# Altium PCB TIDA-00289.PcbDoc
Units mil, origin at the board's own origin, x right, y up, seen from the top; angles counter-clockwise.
Board outline 1181.1 x 984.25 mil, 4 copper layers (Top Layer, MidLayer1 (GND), MidLayer2 (PWR), Bottom Layer), stack 90 mil thick; 82 components, 47 nets, 196 pads, 38 vias.
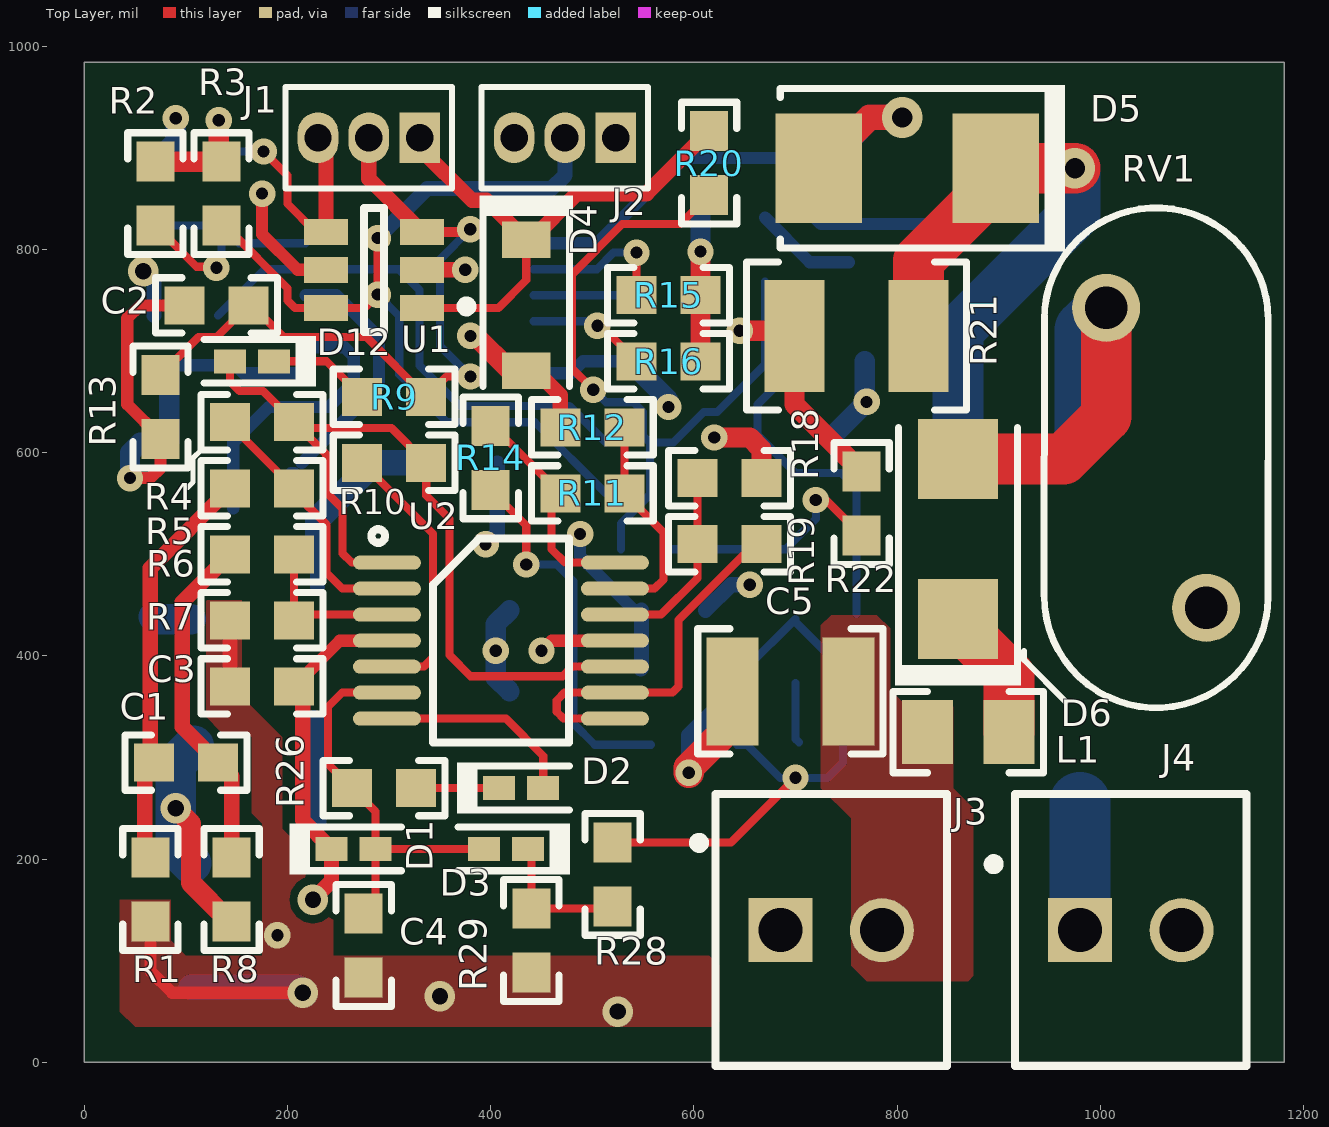
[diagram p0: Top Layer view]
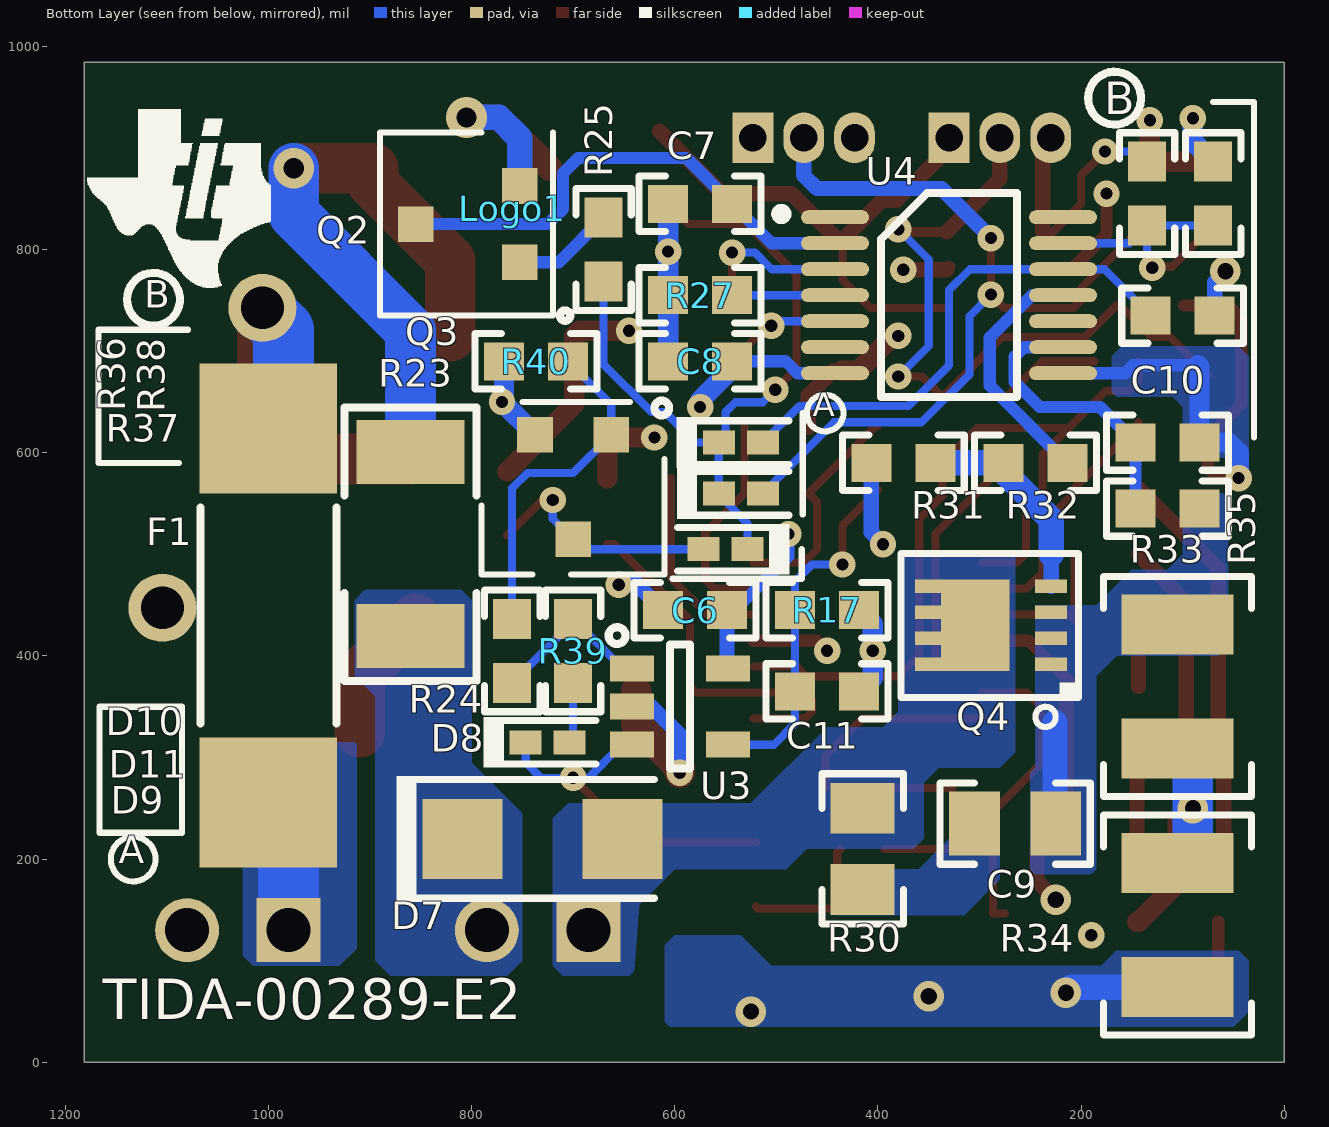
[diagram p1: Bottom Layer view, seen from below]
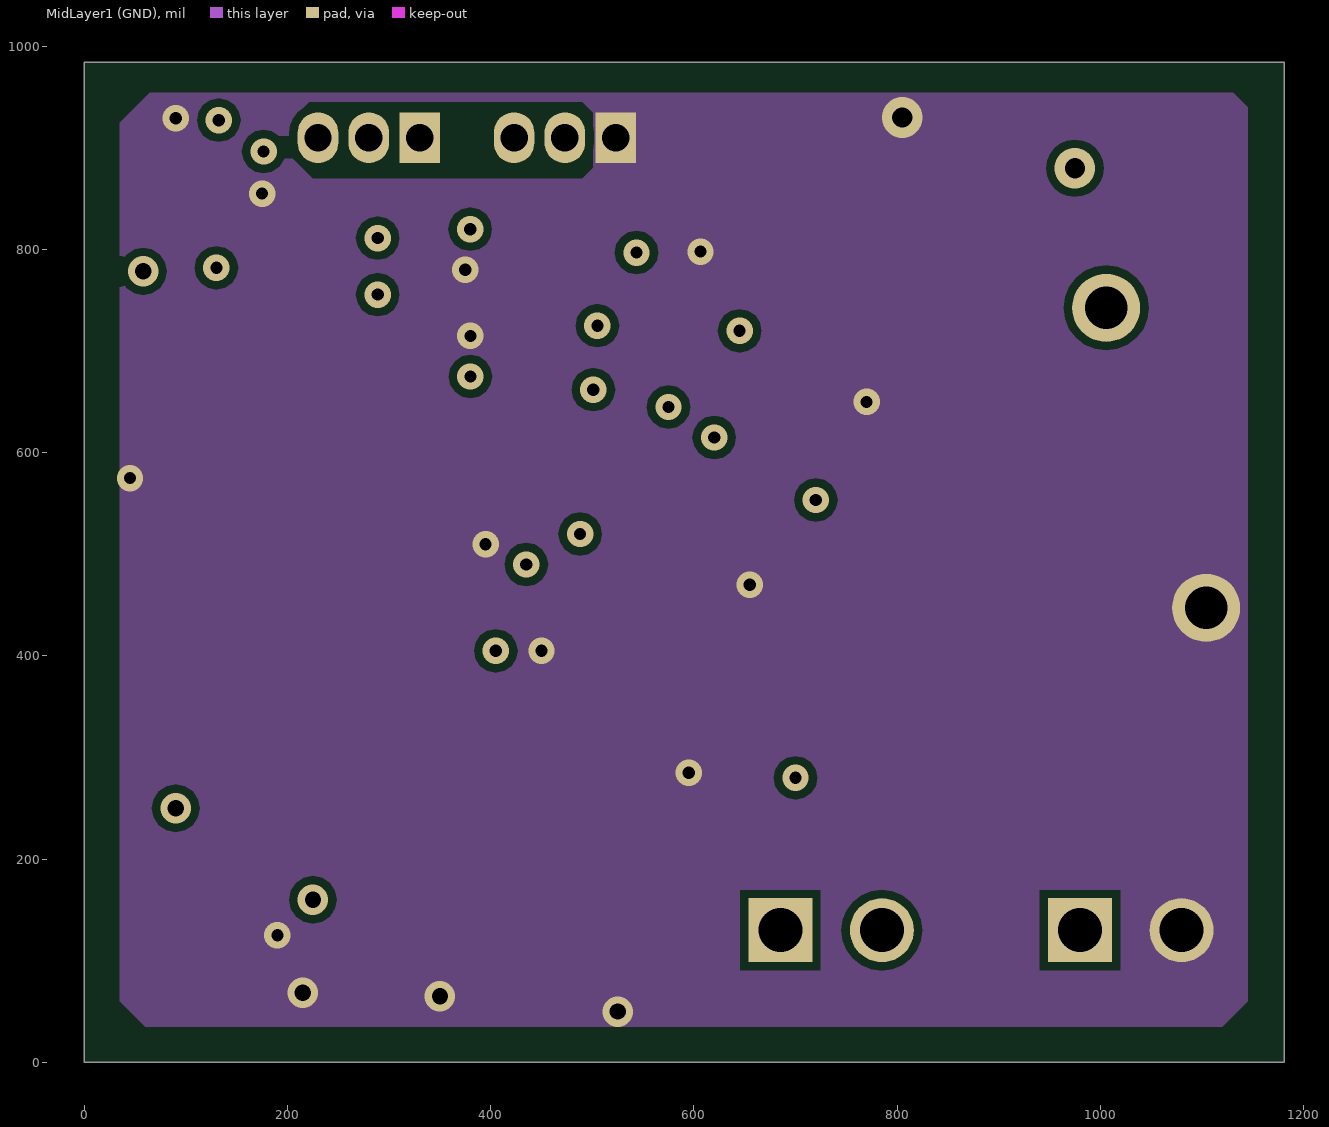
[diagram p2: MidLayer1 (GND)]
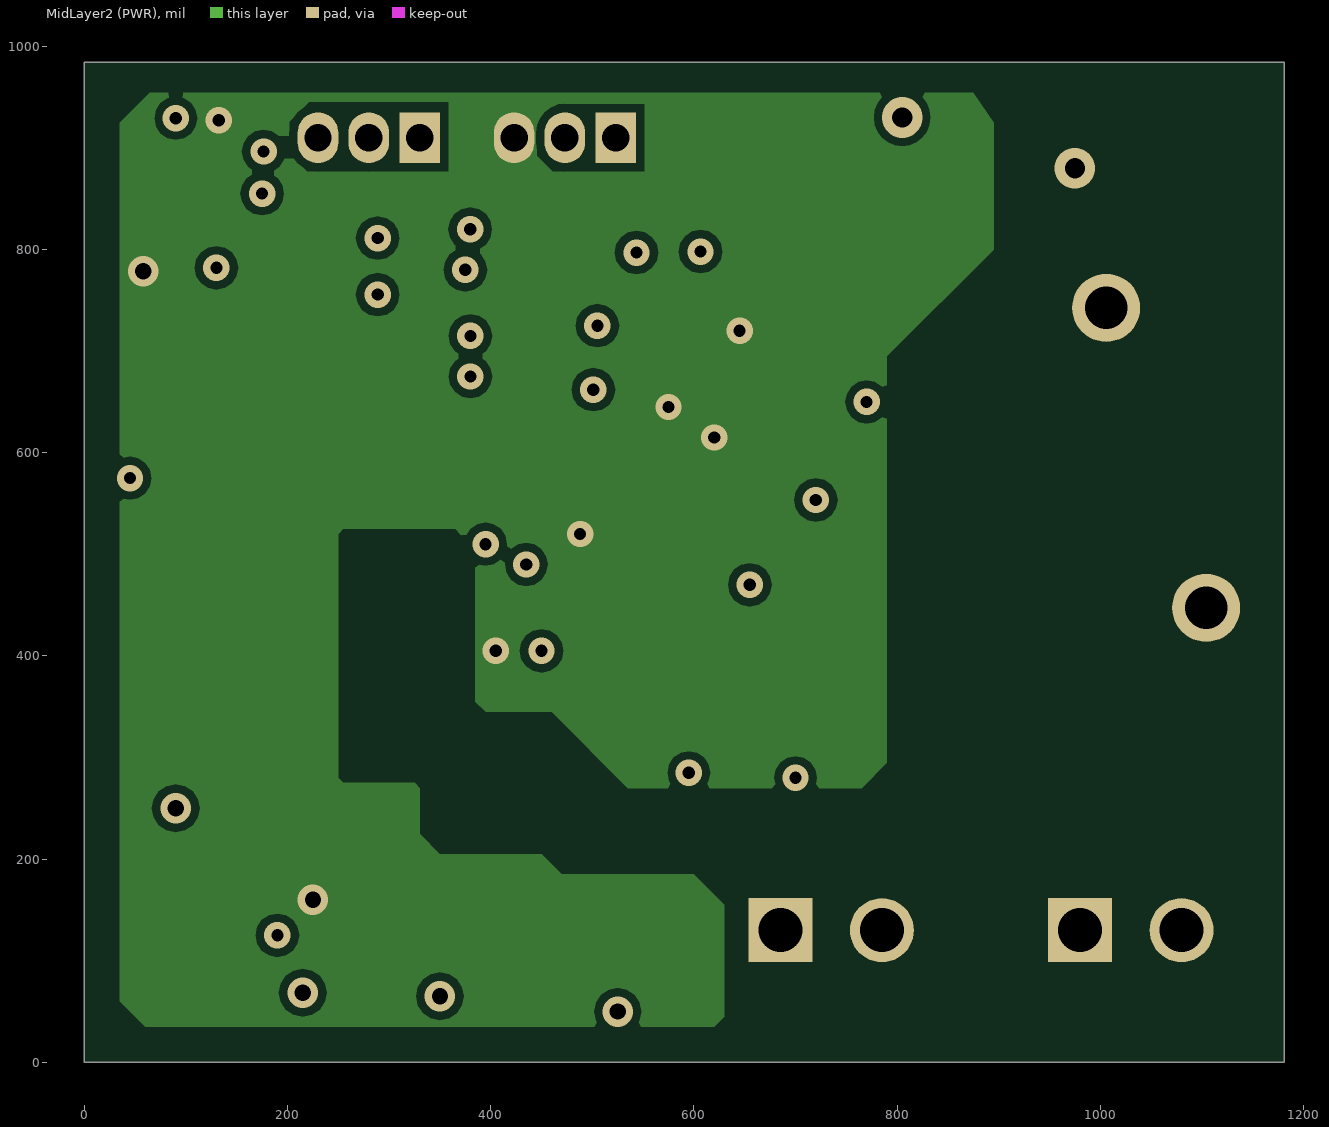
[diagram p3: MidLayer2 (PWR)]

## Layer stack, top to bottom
Top Layer: signal copper 1.4
Dielectric: core 59.2, FR-4, Dk 4.8
MidLayer1 (GND): signal copper 1.4
Dielectric: prepreg 12.6, FR-4, Dk 4.8
MidLayer2 (PWR): signal copper 1.4
Dielectric: core 12.6, FR-4, Dk 4.8
Bottom Layer: signal copper 1.4

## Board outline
0,0 1181.1,0 1181.1,984.25 0,984.25

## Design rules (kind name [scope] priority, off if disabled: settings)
AcuteAngle [All] p1: minimum=4.50000000000000E+0001 checktracksonly=FALSE
AssemblyTestPointUsage [All] p1: valid=2
Clearance "Less Than 9 mils from PAD to PAD" [(InPadClass('Less than 9 Mil Clearance')) vs (InPadClass('All Pads'))] p1: gap=7
Clearance "SMT Pin Via" [IsVia vs IsSMTPin] p2: gap=8
Clearance "Via to Via" [IsVia vs IsVia] p3: gap=8
Clearance Poly_Poly [InPolygon vs InPolygon] p4: gap=15
Clearance "Poly_ All" [InPolygon vs IsTrack and IsThruPin and IsSMTPin and IsThruPin] p5: gap=12
Clearance [All] p6: gap=8
ComponentClearance ComponentClearance_Shunt [InComponentClass('Header') vs InComponentClass('Shunt')] p1: gap=0 collisioncheckmode=3 verticalgap=0 showdistances=FALSE
ComponentClearance ComponentClearance_Logo [InComponentClass('Logo')] p2: gap=50 collisioncheckmode=3 verticalgap=10 showdistances=FALSE
ComponentClearance ComponentClearance_ScrewToNut [(HasFootprint('NY PMS 440 0025 PH')) vs (HasFootprint('Keystone_1902C'))] p3: gap=5 collisioncheckmode=3 verticalgap=10 showdistances=FALSE
ComponentClearance ComponentClearance_MountingHoles [InComponentClass('Mounting Holes')] p4: gap=250 collisioncheckmode=3 verticalgap=100000 showdistances=FALSE
ComponentClearance ComponentClearance_SmallPassives [HasFootprint('0201*') or HasFootprint('0402*') or HasFootprint('0508') or HasFootprint('0603*') or HasFootprint('0612') or HasFootprint('0805*') or HasFootprint('0815*') or HasFootprint('0830*') or HasFootprint('1206*') or HasFootprint('1210*') or HasFootprint('1808*') or HasFootprint('1812*') or HasFootprint('1825*') or HasFootprint('2010*') or HasFootprint('2220*') or HasFootprint('2225*') or HasFootprint('2512*') or HasFootprint('2728*') or HasFootprint('3518*') vs HasFootprint('0201*') or HasFootprint('0402*') or HasFootprint('0508') or HasFootprint('0603*') or HasFootprint('0612') or HasFootprint('0805*') or HasFootprint('0815*') or HasFootprint('0830*') or HasFootprint('1206*') or HasFootprint('1210*') or HasFootprint('1808*') or HasFootprint('1812*') or HasFootprint('1825*') or HasFootprint('2010*') or HasFootprint('2220*') or HasFootprint('2225*') or HasFootprint('2512*') or HasFootprint('2728*') or HasFootprint('3518*')] p5: gap=20 collisioncheckmode=3 verticalgap=10 showdistances=FALSE
ComponentClearance ComponentClearance_THtoSMT [IsThruComponent vs IsSMTComponent] p6: gap=100 collisioncheckmode=3 verticalgap=30 showdistances=FALSE
ComponentClearance ComponentClearance_THtoTH [IsThruComponent vs IsThruComponent] p7: gap=118.11 collisioncheckmode=3 verticalgap=30 showdistances=FALSE
ComponentClearance [All] p8: gap=40 collisioncheckmode=3 verticalgap=10 showdistances=FALSE
DiffPairsRouting [All] p1: maxlimit=100 minlimit=10 mostfreqgap=10 maxuncoupledlength=1000
FabricationTestPointUsage TestPointUsage [All] p1: valid=2 allowmultiple=FALSE
FabricationTestpoint Testpoint [All] p1: side=3 testpointundercomponent=TRUE minsize=40 maxsize=100 preferedsize=60 minholesize=0 maxholesize=40 preferedholesize=32 testpointgrid=1 allowsidetop=TRUE allowsidebottom=TRUE usegrid=TRUE gridtolerance=0.01
FanoutControl Fanout_LCC [IsLCC] p1: bgadir=Out bgaviamode=Centered fanoutstyle=Auto fanoutdirection=Alternating viagrid=1 // Fanout_LCC (Default Rule)
FanoutControl Fanout_BGA [IsBGA] p2: bgadir=Out bgaviamode=Centered fanoutstyle=Auto fanoutdirection=Alternating viagrid=1 // Fanout_BGA (Default Rule)
FanoutControl Fanout_Default [All] p4: bgadir=Out bgaviamode=Centered fanoutstyle=Auto fanoutdirection=Alternating viagrid=1 // Fanout_Default (Default Rule)
FanoutControl Fanout_Small [(CompPinCount < 5)] p5: bgadir=Out bgaviamode=Centered fanoutstyle=Auto fanoutdirection=OutThenIn viagrid=1 // Fanout_Small (Default Rule)
HoleSize [All] p1: absolutevalues=TRUE maxlimit=251 minlimit=8 maxpercent=80.000 minpercent=20.000
MinimumAnnularRing MinimumAnnularRing_ThermalPadVias [IsVia and InAnyComponent] p1: minimumring=5.91
MinimumAnnularRing [All] p2: minimumring=5.91
MinimumSolderMaskSliver MinimumSolderMaskSliver_Logo [InComponentClass('Logo') vs InComponentClass('Logo')] p1: minsoldermaskwidth=0.7
MinimumSolderMaskSliver [All] p2: minsoldermaskwidth=3.94
PlaneConnect [All] p1: planeconnectstyle=Relief reliefexpansion=10 reliefentries=4 reliefconductorwidth=10 reliefairgap=10
PolygonConnect [All] p1: connectstyle=Direct reliefconductorwidth=10 reliefentries=4 polygonreliefangle="90 Angle" airgapwidth=10
RoutingVias [All] p1: holewidth=12 width=26 viastyle="Through Hole" minholewidth=12 minwidth=26 maxholewidth=20 maxwidth=40
SMDToCorner [All] p1: distance=30000
SilkToSilkClearance [All] p1: silktosilkclearance=5
SilkscreenOverComponentPads [All] p1: minsilkscreentomaskgap=5
SolderMaskExpansion [All] p1: expansion=2.5
Width [All] p1: maxlimit=100 minlimit=8 preferedwidth=8 checkconnectedcopper=TRUE
14 further rules are at their usual default settings.

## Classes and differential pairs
pad class "Less than 9 Mil Clearance": U1-1 U1-2 U1-3 U1-4 U1-5 U1-6 U1-7 U1-8 U1-9 U1-10 U1-11 U1-12 U1-13 U1-14 U2-1 U2-2 U2-3 U2-4 U2-5 U2-6 U2-7 U2-8
component class Pg2-Main: C1 C2 C3 C4 C5 C6 C7 C8 C9 C10 C11 D1 D2 D3 D4 D5 D6 D7 D8 D9 D10 D11 D12 F1 J1 J2 J3 J4 L1 Q2 Q3 Q4 R1 R2 R3 R4 R5 R6 R7 R8 R9 R10 R11 R12 R13 R14 R15 R16 R17 R18 R19 R20 R21 R22 R23 R24 R25 R26 R27 R28 R29 R30 R31 R32 R33 R34 R35 R36 R37 R38 R39 R40 RV1 U1 U2 U3 U4
component class AssemblyNote: ZZ1 ZZ2 ZZ3 ZZ4
component class Pg3_Hardware_ANSI-B: !PCB Logo1 ZZ1 ZZ2 ZZ3 ZZ4
component class Logo: Logo1

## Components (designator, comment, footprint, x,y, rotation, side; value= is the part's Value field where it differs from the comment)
C1 "06035A101JAT2A" 0603 100,295 r180 top (schematic designator C9)
C2 "GRM188R71E104KA01D" 0603 130,745 r180 top (schematic designator C7)
C3 "GRM188R71E104KA01D" 0603 175,370 r0 top (schematic designator C5)
C4 "GRM188R71E474KA12D" 0603 275,115 r270 top (schematic designator C6)
C5 "C3225X7R2A105K200AA" 1210 695,365 r180 top (schematic designator C4)
C6 "GRM188R71E104KA01D" 0603 580,445 r180 bottom (schematic designator C10)
C7 "C0603C105K8PACTU" 0603 575,845 r180 bottom (schematic designator C2)
C8 "GMK107BJ105KA-T" 0603 575,690 r0 bottom (schematic designator C1)
C9 "08051C103KAT2A" 0805_HV 265,235 r180 bottom (schematic designator C7)
C10 "06035A101JAT2A" 0603 115,610 r180 bottom (schematic designator C3)
C11 "GRM188R71E472KA01D" 0603 450,365 r180 bottom
D1 "NSR0520V2T1G" SOD-523#1 265,210 r0 top (schematic designator D11)
D2 "NSR0520V2T1G" SOD-523#2 430,270 r0 top (schematic designator D6)
D3 "NSR0520V2T1G" SOD-523#2 415,210 r180 top (schematic designator D5)
D4 "MMSZ5240B-7-F" SOD-123 435,745 r270 top (schematic designator D10)
D5 "SMBJ5357B-TP" SMB 810,880 r180 top (schematic designator D3)
D6 "CMR1U-02M" SMA 860,515 r90 top (schematic designator D5)
D7 "US1B-13-F" SMA 730,220 r180 bottom (schematic designator D2)
D8 "NSR0520V2T1G" SOD-523#2 725,315 r180 bottom (schematic designator D7)
D9 "NSR0520V2T1G" SOD-523#2 550,505 r0 bottom
D10 "NSR0520V2T1G" SOD-523#2 535,610 r180 bottom (schematic designator D1)
D11 "NSR0520V2T1G" SOD-523#2 535,560 r180 bottom (schematic designator D8)
D12 "NSR0520V2T1G" SOD-523#1 165,690 r180 top
F1 "0443.500DR" FUSE_0443 1000,440 r270 bottom
J1 "800-10-003-10-001000" CONNECTOR_GRPB031VWVN-RC 330,910 r180 top (schematic designator J5)
J2 "800-10-003-10-001000" CONNECTOR_GRPB031VWVN-RC 523,910 r180 top (schematic designator J4)
J3 "282834-2" TEC_282834-2 735,130 r0 top (schematic designator J2)
J4 "282834-2" TEC_282834-2 1030,130 r0 top (schematic designator J1)
L1 "LQM21PN2R2NGC" 0805_HV 870,325 r180 top
Logo1 "Texas Instruments" TI_Stacked_SolderMask_Small 760,840 r180 bottom
Q2 "TR-BC850" SOT-23 805,825 r90 bottom
Q3 "TR-BC850" SOT-23 700,565 r0 bottom
Q4 "BSZ440N10NS3 G" PG-TSDSON-8 290,430 r0 bottom (schematic designator Q1)
R1 "RC0603FR-071KL" 0603 65,170 r270 top (schematic designator R33)
R2 "RT0603BRD0710KL" 0603 70,855 r90 top (schematic designator R11)
R3 "RT0603BRD0710KL" 0603 135,855 r270 top (schematic designator R13)
R4 "CRCW0603100KFKEA" 0603 175,630 r180 top (schematic designator R16)
R5 "RC0603FR-071KL" 0603 175,565 r180 top (schematic designator R20)
R6 "RC0603FR-071KL" 0603 175,500 r180 top (schematic designator R24)
R7 "CRCW0603100KFKEA" 0603 175,435 r0 top (schematic designator R25)
R8 "RC0603FR-071KL" 0603 145,170 r90 top (schematic designator R32)
R9 "RC0603FR-071KL" 0603 305,655 r0 top (schematic designator R1)
R10 "RT0603BRD0710KL" 0603 305,590 r0 top (schematic designator R38)
R11 "RC0603FR-071KL" 0603 500,560 r180 top (schematic designator R31)
R12 "CRCW0603100KFKEA" 0603 500,625 r0 top (schematic designator R35)
R13 "CRCW0603100KFKEA" 0603 75,645 r90 top (schematic designator R29)
R14 "RC0603FR-071KL" 0603 400,595 r270 top (schematic designator R30)
R15 "CRCW0603100KFKEA" 0603 575,755 r0 top (schematic designator R4)
R16 "CRCW06030000Z0EA" 0603 575,690 r0 top (schematic designator R2)
R17 "CRCW0603100KFKEA" 0603 450,445 r0 bottom (schematic designator R37)
R18 "CRCW0603100KFKEA" 0603 635,575 r180 top
R19 "RC0603FR-071KL" 0603 635,510 r180 top (schematic designator R23)
R20 "RC0603FR-071KL" 0603 615,885 r90 top (schematic designator R36)
R21 "MCR25JZHJ000" 1210M 760,715 r0 top (schematic designator R7)
R22 "CRCW060320K0FKEA" 0603 765,550 r270 top (schematic designator R15)
R23 "CRCW2010430KJNEF" 2010 860,510 r270 bottom (schematic designator R8)
R24 "RT0603BRD0710KL" 0603 760,405 r270 bottom (schematic designator R22)
R25 "CRCW0603196KFKEA" 0603 670,800 r90 bottom (schematic designator R34)
R26 "CRCW0603100RFKEA" 0603 295,270 r180 top (schematic designator R28)
R27 "CRCW060351R1FKEA" 0603 575,755 r0 bottom (schematic designator R3)
R28 "RT0603BRD0710KL" 0603 520,185 r90 top (schematic designator R26)
R29 "CRCW0603196KFKEA" 0603 440,120 r90 top (schematic designator R27)
R30 "RT0805BRD07100RL" 0805_HV 415,210 r90 bottom (schematic designator R14)
R31 "RC0603FR-071KL" 0603 375,590 r180 bottom (schematic designator R12)
R32 "CRCW06030000Z0EA" 0603 245,590 r180 bottom (schematic designator R10)
R33 "MCR25JZHFLR390" 1210M 105,370 r90 bottom (schematic designator R6)
R34 "MCR25JZHFLR200" 1210M 105,135 r90 bottom (schematic designator R19)
R35 "RC0603FR-071KL" 0603 115,545 r180 bottom (schematic designator R5)
R36 "RT0603BRD0710KL" 0603 135,855 r90 bottom (schematic designator R21)
R37 "CRCW060320K0FKEA" 0603 100,735 r180 bottom (schematic designator R9)
R38 "CRCW06032K00JNEA" 0603 70,855 r270 bottom (schematic designator R17)
R39 "CRCW06030000Z0EA" 0603 700,405 r90 bottom
R40 "RT0603BRD0710KL" 0603 736.5,690 r180 bottom
RV1 "V100ZA4P" VAR_V100ZA4P 1055,595 r90 top
U1 "SMS12T1G" DBV0006A_N 285,780 r180 top (schematic designator U3)
U2 "OPA4170AIPW" PW0014A_N 410,415 r0 top (schematic designator U4)
U3 "TLV271IDBVR" DBV0005A_N 595,350 r180 bottom (schematic designator U2)
U4 "DRV110APW" PW0014A_N 330,755 r180 bottom (schematic designator U1)
ZZ1 "This Assembly Note is for PCB labels only" AssemblyNoteLabel -250,1480 r0 top
ZZ2 "These assemblies are ESD sensitive, ESD precautions shall be observed." AssemblyNote -250,1410 r0 top
ZZ3 "These assemblies must be clean and free from flux and all contaminants. Use of no clean flux is not acceptable." AssemblyNote -250,1340 r0 top
ZZ4 "These assemblies must comply with workmanship standards IPC-A-610 Class 2, unless otherwise specified." AssemblyNote -250,1270 r0 top

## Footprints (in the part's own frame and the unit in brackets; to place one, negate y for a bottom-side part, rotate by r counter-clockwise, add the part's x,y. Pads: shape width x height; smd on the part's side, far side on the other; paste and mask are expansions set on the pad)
0603 [mm] "0603 from SM-752 data"
  rect 1x0.95 smd: 1(-0.8,0) 2(0.8,0)
  silkscreen extent -1.52,-0.69 1.52,0.69, body extent -0.87,-0.47 0.87,0.47, height 0.85
0805_HV [mil] "0805 with 30mil clearance between pads"
  rect 50x63 smd: 1(-40,0) 2(40,0)
  silkscreen extent -74,-40 74,40, body extent -43,-29 43,29, height 43
1210 [mm] "1210 from SM-752 data"
  rect 1.3x2.7 smd: 1(-1.45,0) 2(1.45,0)
  silkscreen extent -2.32,-1.57 2.32,1.57, body extent -1.7,-1.35 1.7,1.35, height 1.35
1210M [mm] "1210 from SM-752 data"
  rect 1.5x2.8 smd: 1(-1.55,0) 2(1.55,0)
  silkscreen extent -2.75,-1.85 2.75,1.85, body extent -1.7,-1.35 1.7,1.35, height 1.35
2010 [mm] "Chip Capacitor, Body 5.08x2.54mm, IPC Medium Density"
  rect 1.6x2.7 smd: 1(-2.3,0) 2(2.3,0)
  silkscreen extent -3.42,-1.65 3.42,1.65, body extent -2.73,-1.45 2.73,1.45, height 1.66
AssemblyNote [mil] "Assembly Note"
AssemblyNoteLabel [mil] "Assembly Note for PCB Labels"
CONNECTOR_GRPB031VWVN-RC [mil] "CONN HEADER .050\" 3POS PCB GOLD"
  rect 40x50 hole 27: 1(0,0)
  oval 40x50 hole 27: 2(50,0) 3(100,0)
  silkscreen extent -32,-50 132,50, body extent -32,-50 132,50, height 150
DBV0005A_N [mm] "SOT23, 5-Leads, Body 2.9x1.6mm, Pitch 0.95mm, Lead Span 2.8mm, IPC Medium Density"
  rect 1.1x0.65 smd: 1(-1.2,0.95) 2(-1.2,0) 3(-1.2,-0.95) 4(1.2,-0.95) 5(1.2,0.95)
  silkscreen extent -0.25,-1.55 0.25,1.55, body extent -1.42,-1.46 1.42,1.46, height 1.08
DBV0006A_N [mm] "SOT23, 6-Leads, Body 2.9x1.6mm, Pitch 0.95mm, Lead Span 2.8mm, IPC Medium Density"
  rect 1.1x0.65 smd: 1(-1.2,0.95) 2(-1.2,0) 3(-1.2,-0.95) 4(1.2,-0.95) 5(1.2,0) 6(1.2,0.95)
  silkscreen extent -2.44,-1.55 0.25,1.55, body extent -1.42,-1.46 1.42,1.46, height 1.11
FUSE_0443 [mm] "LITTELFUSE"
  rect 3.25x3.43 smd: 1(-4.675,0) 2(4.675,0)
  silkscreen extent -2.7,-1.7 2.7,1.7, body extent -5.05,-1.56 5.05,1.56, height 3.12
PG-TSDSON-8 [mm] "Infineon recommended land pattern"
  rect 0.8x0.34 smd: 1(-1.538,0.975) 2(-1.538,0.325) 3(-1.538,-0.325) 4(-1.538,-0.975)
  rect 0.65x0.34 smd: 5(1.538,-0.975) 6(1.538,-0.325) 7(1.538,0.325) 8(1.538,0.975)
  rect 1.71x2.29 smd: 9(0.358,0)
  silkscreen extent -2.22,-1.8 2.22,1.8, body extent -1.7,-1.7 1.7,1.7, height 1.1
PW0014A_N [mm] "TSOP, 14-Leads, Body 5x4.4mm, Pitch 0.65mm, IPC Medium Density"
  oval 1.7x0.35 smd: 1(-2.85,1.95) 2(-2.85,1.3) 3(-2.85,0.65) 4(-2.85,0) 5(-2.85,-0.65) 6(-2.85,-1.3) 7(-2.85,-1.95) 8(2.85,-1.95) 9(2.85,-1.3) 10(2.85,-0.65) 11(2.85,0) 12(2.85,0.65) 13(2.85,1.3) 14(2.85,1.95)
  silkscreen extent -1.7,-2.55 1.7,2.55, body extent -3.21,-2.5 3.21,2.5, height 0.98
SMA [mm] "Molded Diode, 2-Leads, Body 4.3x2.6mm, IPC Medium Density, based on OnSemi component dimensions and land pattern"
  rect 2x2 smd: 1(-2,0) 2(2,0)
  silkscreen extent -3.66,-1.57 2.79,1.57, body extent -2.6,-1.3 2.6,1.3, height 2.42
SMB [mil] "Molded Diode, 2-Leads, Body 5.4x3.6mm, IPC Medium Density, based on OnSemi component dimensions"
  rect 85x107.99 smd: 1(-87.01,0) 2(87.01,0)
  silkscreen extent -155,-82 125,82, body extent -106,-71 106,71, height 91
SOD-123 [mm] "On Semi recommended land pattern"
  rect 0.915x1.22 smd: 1(-1.637,0) 2(1.637,0)
  silkscreen extent -2.74,-1.17 2.03,1.17, body extent -1.93,-0.9 1.93,0.9, height 1.35
SOD-523#1 [mm] "NXP Semiconductor recommended land pattern, nominal STEP model"
  rect 0.8x0.6 smd: 1(-0.55,0) 2(0.55,0)
  silkscreen extent -1.6,-0.64 1.2,0.64, body extent -0.8,-0.4 0.8,0.4, height 0.72
SOD-523#2 [mm] "NXP Semiconductor recommended land pattern, nominal STEP model"
  rect 0.8x0.6 smd paste+0: 1(-0.55,0) 2(0.55,0)
  silkscreen extent -1.6,-0.63 1.2,0.64, body extent -0.8,-0.4 0.8,0.4, height 0.72
SOT-23 [mil]
  rect 35x35 smd: 1(-37.5,-52.5) 2(37.5,-52.5) 3(0,50)
TEC_282834-2 [mm] "TEC"
  rect 1.6x1.6 hole 1.1: 1(-1.27,0)
  round 1.6 hole 1.1: 2(1.27,0)
  silkscreen extent -3.4,-3.4 2.9,3.4, body extent -2.77,-3.25 2.77,3.25, height 10.01
TI_Stacked_SolderMask_Small [mil]
  silkscreen extent -418,-78 -237,98
VAR_V100ZA4P [mil] "VARISTOR  DISC 10MM"
  round 67 hole 42: 1(-147.64,-49.21) 2(147.64,49.21)
  silkscreen extent -246,-110 246,110, body extent -245,-110 245,110, height 630

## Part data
C1 C10: "CAP, CERM, 100pF, 50V, +/-5%, C0G/NP0, 0603"
C2 C3 C6: "CAP, CERM, 0.1uF, 25V, +/-10%, X7R, 0603"
C4: "CAP, CERM, 0.47uF, 25V, +/-10%, X7R, 0603"
C5: "CAP, CERM, 1uF, 100V, +/-10%, X7R, 1210"
C7: "CAP, CERM, 1uF, 10V, +/-10%, X5R, 0603"
C8: "CAP, CERM, 1uF, 35V, +/-10%, X5R, 0603"
C9: "CAP, CERM, 0.01uF, 100V, +/-10%, X7R, 0805"
C11: "CAP, CERM, 4700pF, 25V, +/-10%, X7R, 0603"
D1 D2 D3 D8 D9 D10 D11 D12: library part SBR0220T5-7, "DIODE SCHOTTKY 20V 0.5A SOD523"
D4: "Diode, Zener, 10V, 500mW, SOD-123"
D5: "Diode, Zener, 20V, 5 W, SMB"
D6: "Diode, Ultrafast, 200V, 1A, SMA"
D7: "Diode, Ultrafast, 100V, 1A, SMA"
F1: "Fuse, 0.5A, 250V, SMD"
J1 J2: "Header, 3x1, 100mil, SMT"
J3 J4: "Terminal Block, 2x1, 2.54mm, TH"
L1: "Inductor, Shielded, Ferrite, 2.2 uH, 0.8A, 0.23 ohm, SMD"
Logo1: library part TI_Logo, "Texas Instrument Corporate Signature"
Q2 Q3: "Transistor, N-Chan GP, 45V, 100mA"
Q4: "MOSFET, N-CH, 100V, 18A, PG-TSDSON-8"
R1 R5 R6 R8 R9 R11 R14 R19 R20 R31 R35: "RES, 1.00k ohm, 1%, 0.1W, 0603"
R2 R3 R10 R24 R28 R36 R40: "RES, 10.0k ohm, 0.1%, 0.1W, 0603"
R4 R7 R12 R13 R15 R17 R18: "RES, 100 k, 1%, 0.1 W, 0603"
R16 R32 R39: "RES, 0 ohm, 5%, 0.1W, 0603"
R21: "RES, 0 ohm, 5%, 0.25W, 1210"
R22 R37: "RES, 20.0k ohm, 1%, 0.1W, 0603"
R23: "RES, 430k ohm, 5%, 0.75W, 2010"
R25 R29: "RES, 196 k, 1%, 0.1 W, 0603"
R26: "RES, 100, 1%, 0.1 W, 0603"
R27: "RES, 51.1, 1%, 0.1 W, 0603"
R30: "RES, 100 ohm, 0.1%, 0.125W, 0805"
R33: "RES, 0.39 ohm, 1%, 0.5W, 1210"
R34: "RES, 0.2 ohm, 1%, 0.5W, 1210"
R38: "RES, 2.0 k, 5%, 0.1 W, 0603"
RV1: library part B72207S2301K101, "VARISTOR 90V 2.5KA DISC 10MM"
U1: "TVS DIODE 12VWM 23VC SC74-6"
U2: "36V, Single-Supply, SOT553, Low-Power OPERATIONAL AMPLIFIERS Value Line Series, PW0014A"
U3: "550 uA/Ch, 3 MHz, Rail-to-Rail Output Operational Amplifier, 2.7 to 16 V, -40 to 125 degC, 5-pin SOT23 (DBV0005A), Green (RoHS & no Sb/Br)"
U4: "POWER SAVING SOLENOID CONTROLLER WITH INTEGRATED SUPPLY REGULATION, PW0014A"
ZZ1: library part AssemblyNoteLabel
ZZ2 ZZ3 ZZ4: library part AssemblyNote

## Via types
v1: diameter 26, hole 12, Top Layer to Bottom Layer, tented both sides, 30 vias
v2: diameter 30, hole 16, Top Layer to Bottom Layer, tented both sides, 6 vias
v3: diameter 40, hole 20, Top Layer to Bottom Layer, tented both sides, 2 vias

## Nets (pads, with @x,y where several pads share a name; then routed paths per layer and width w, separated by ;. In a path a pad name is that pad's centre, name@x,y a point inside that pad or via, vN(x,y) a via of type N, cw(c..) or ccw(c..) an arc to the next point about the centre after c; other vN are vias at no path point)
AOUT: C2.1 J1.2 R9.2 R13.2 U1.3 | length 711.7
  Top Layer w8: R13.2 112.32,713.81 130.31,713.81 C2.1 165,745 196.19,713.81 277.68,713.81 R9.2 356.5,675 v1(380,675)
  Top Layer w10: U1.3 377.2,817.4 v1(379.8,820)
  Top Layer w15: J1.2 280,869.65 U1.3
  Bottom Layer w8: v1(379.8,820) 379.64,820 350,790.36 350,705 v1(380,675)
COIL+: C5.1 D7.1 J3.2 L1.2 R23.2
COIL-: D7.2 J3.1 Q4.5 Q4.6 Q4.7 Q4.8 Q4.9 R30.2
EN: J1.3 R36.2 U1.4 | length 251.9
  Top Layer w8: v1(176.5,896.5) 200,872.99 200,845 227.6,817.4 U1.4
  Top Layer w15: J1.3 237.76,902.24 U1.4
  Bottom Layer w8: R36.2 145,896.5 v1(176.5,896.5)
FAULT_IND: D9.1 D10.1 D11.1 R20.1 R25.1 | length 723.9
  Top Layer w8: v1(501,662) 480,683 480,775.59 529.41,825 586.5,825 R20.1
  Bottom Layer w8: v1(501,662) 513.35,649.65 540.35,649.65 550,640 550,616.65 D10.1 ; D9.1 528.35,530.47 556.65,558.78 D11.1 D10.1 ; R25.1 670,687 623,640 609.64,640 579.64,610 D10.1
GND: C2.2 C3.1 C4.2 C5.2 C6.1 C7.1 C8.2 C10.2 D4.2 D5.2 J2.1 J4.2 Q2.2 Q3.2 R1.2 R7.1 R12.1 R13.1 R15.2 R16.2 R27.2 R29.1 R31.1 R34.1 R38.1 R40.1 RV1.1 U1.2 U1.5 U2.11 U3.2 U4.8 | length 2237.9
  Top Layer w12: v1(45,575) 65,575 75,585 R13.1 75,615 42.3,647.7 42.3,732.3 55,745 C2.2 ; R1.2 65,90 86.5,68.5 v2(215,68.5) ; v1(175,855) 175,815 210,780 U1.5 ; U1.2@329.65,782.59 U1.2 ; v1(450,405) 460,415 U2.11
  Top Layer w15: C3.1 R7.1 ; U1.2 v1(375,780) ; D4.2 444.47,680.53 468.5,656.5 R12.1
  Top Layer w20: v1(380,715) 385,715 419.47,680.53 D4.2 ; R16.2 v1(606.5,798)
  Top Layer w25: D5.2 772.99,930 v3(805,930)
  Top Layer w30: v1(595,285) 595,290 637.91,332.91 C5.2
  Bottom Layer w12: 85,686 149,686 156.77,678.23 U4.8
  Bottom Layer w15: v1(395,510) 406.5,521.5 R31.1 ; v1(595,285) 595,322 623,350 U3.2 ; C6.1 636.5,470 v1(655,470)
  Bottom Layer w20: v1(45,575) 45,600 55,610 C10.2 83.5,684.5 85,686 ; R38.1 90,906.5 v1(90,929.25) ; C8.2 v1@606.5,786.5 ; v1(606.5,798) C7.1 ; Q3.2 v1(770,650) 767.99,652.01 R40.1
  Bottom Layer w25: R34.1 209.53,73.98 v2(215,68.5) ; Q2.2 752.5,909.51 772.99,930 v3(805,930)
  other v1: 190,125
  other v2: 525,50 350,65
ITRIP: R24.2 R39.2 U3.1 | length 165.9
  Bottom Layer w8: U3.1 650.91,387.4 R39.2 700,433.5 R24.2
NetC1_1: C1.1 R6.2 R8.2 | length 338.1
  Top Layer w15: R6.2 96.5,452.99 96.5,330 C1.1 145,281.5 R8.2
NetC1_2: C1.2 R1.1 R5.2 | length 403.5
  Top Layer w15: R1.1 59.5,207 59.5,286 C1.2 65,298.5 65,486.5 R5.2
NetC4_1: C4.1 D1.2 D3.2 R26.2 U2.6 | length 404.6
  Top Layer w8: C4.1 286.5,146.5 286.65,146.65 D1.2 ; U2.6 253.82,363.82 240,350 240,293.5 R26.2 286.65,246.85 D1.2 ; D3.2 D1.2
NetC7_2: C7.2 Q2.3 U4.2 | length 494.9
  Bottom Layer w12: U4.2 504.69,806.18 C7.2 588.5,890 695,890 710,875 710,840 725,825 Q2.3
NetC9_1: C9.1 R30.1
NetC9_2: C9.2 Q4.1 Q4.2 Q4.3 R33.2 R35.2 | length 137.3
  Bottom Layer w25: C9.2 225.7,235.7 225.7,334.51
  Bottom Layer w30: R33.2@68.5,438.43 70.91,436.02 R33.2@105,436.02
NetC10_1: C10.1 R35.1 U4.9 | length 284.8
  Bottom Layer w12: R35.1 C10.1 181.5,645 240.68,645 265.26,669.58 265.26,694.74 256.18,703.82 U4.9
NetC11_1: C11.1 R14.2 R17.2 U3.4 | length 366.1
  Top Layer w8: R14.2 435,528.5 v1(435,490)
  Bottom Layer w8: v1(435,490) 465,490 481.5,473.5 R17.2 C11.1 481.5,333.5 502.4,312.6 U3.4 U3.4@557.6,312.6
NetD2_1: D2.1 R26.1 | length 81.9
  Top Layer w8: R26.1 D2.1
NetD2_2: D2.2 U2.7 | length 200.6
  Top Layer w8: U2.7 415,338.23 451.65,301.57 D2.2
NetD3_1: D3.1 R28.1 R29.2 | length 140.7
  Top Layer w8: D3.1 440,206.65 R29.2 517.99,151.5 R28.1
NetD4_1: D4.1 J1.1 R20.2 U1.1 | length 530.4
  Top Layer w8: U1.1 407.6,742.6 435,770 D4.1
  Top Layer w15: J1.1 330,900 381.5,848.5 395.97,848.5 D4.1 439.47,809.47 485,855 553.5,855 R20.2
NetD5_1: D5.1 R21.2 R23.1 | length 601.5
  Top Layer w50: R21.2 821.02,789.02 897.01,865.01 D5.1 v3(975,880)
  Bottom Layer w50: R23.1 860,720 975,835 v3(975,880)
NetD6_1: D6.1 L1.1 | length 134
  Top Layer w50: D6.1@855,436.26 910,381.26 L1.1
NetD6_2: D6.2 F1.1 RV1.2 | length 404.3
  Top Layer w50: D6.2 963.74,593.74 1005.79,635.79 RV1.2
  Bottom Layer w50: F1.1@980,624.06 F1.1@985,629.06
  Bottom Layer w60: F1.1@985,624.06 985,629.06 985,720.9 1005.79,741.69 RV1.2
NetD8_1: D8.1 R28.2 U3.3 | length 350.3
  Top Layer w8: R28.2 636.5,216.5 v1(700,280)
  Bottom Layer w8: U3.3 652.4,312.6 685,280 v1(700,280) 731.5,280 746.65,295.15 D8.1
NetD8_2: D8.2 R39.1 | length 59.9
  Bottom Layer w8: R39.1 700,318.35 D8.2
NetD9_2: D9.2 Q3.3 R22.2 | length 238.8
  Top Layer w8: v1(720,553.5) 730,553.5 R22.2
  Bottom Layer w8: D9.2 690,505 Q3.3 720,535 v1(720,553.5)
NetD12_1: D12.1 R9.1 | length 101.3
  Top Layer w8: D12.1 238.5,690 R9.1
NetD12_2: D12.2 R4.1 R10.2 U2.1 U2.10 | length 808.6
  Top Layer w8: D12.2 143.35,670.15 152.8,660.7 175.8,660.7 R4.1 R4.1@212.2,624.3 ; U2.1 263.23,491.77 254.18,500.82 254.18,545 238.18,561 238.18,598.31 R4.1@212.2,624.3 ; U2.10 480,389.41 470.59,380 380,380 359.26,400.74 359.26,535 336.5,557.76 R10.2 302.2,624.3 R4.1@212.2,624.3
NetF1_2: F1.2 J4.1 | length 125.9
  Bottom Layer w60: J4.1 F1.2@980,255.94
NetQ2_1: Q2.1 R25.2 | length 100.7
  Bottom Layer w12: R25.2 714,787.5 Q2.1
NetQ3_1: Q3.1 R24.1 R40.2 | length 332.9
  Bottom Layer w8: R40.2 662.5,647.5 Q3.1 700,580 745,580 760,565 R24.1@760,441.5
NetQ4_4: Q4.4 R31.2 R32.1 | length 208.1
  Bottom Layer w15: Q4.4 229.47,500
  Bottom Layer w25: 229.47,500 229.47,534.47 276.5,581.5 R32.1 R31.2
NetR2_1: R2.1 R36.1 R38.2 U4.13 | length 275.7
  Top Layer w8: R2.1 110.5,783 129,783 v1(130,782)
  Bottom Layer w8: R38.2 R36.1 ; v1(130,782) 135,787 R36.1 ; U4.13 152.32,806.18 R36.1
NetR4_2: R4.2 R5.1 U2.2 | length 253.5
  Top Layer w8: R4.2 143.5,627.99 R5.1 206.5,560.88 238.18,529.19 238.18,481.82 253.82,466.18 U2.2
NetR6_1: R6.1 R7.2 U2.3 | length 158.6
  Top Layer w8: R6.1 R7.2 212.09,440.59 U2.3
NetR8_1: R8.1 R33.1 R34.2 | length 264.2
  Top Layer w20: v2(90,250) 105,235 105,176.7 143.2,138.5 R8.1
  Bottom Layer w40: R34.2 90,211.02 v2(90,250) 90,293.98 R33.1 R33.1@107.5,311.48
NetR10_1: R10.1 U2.5 | length 269.8
  Top Layer w8: R10.1 343.26,520.24 343.26,398.26 334.41,389.41 U2.5
NetR11_1: R11.1 R12.2 U2.13 | length 217.4
  Top Layer w8: U2.13 561.18,466.18 570,475 570,521.5 R11.1 R12.2
NetR11_2: R11.2 R14.1 U2.14 | length 222.3
  Top Layer w8: R14.1 402.01,626.5 R11.2 460,551.5 460,505 473.23,491.77 U2.14
NetR15_1: R15.1 U4.3 | length 150.1
  Top Layer w8: R15.1 v1(543.5,797)
  Bottom Layer w8: U4.3 504.55,780.59 520.96,797 v1(543.5,797)
NetR16_1: R16.1 U4.5 | length 117.6
  Top Layer w8: v1(505,725) 508.5,725 R16.1
  Bottom Layer w8: U4.5 500.59,729.41 v1(505,725)
NetR18_2: R18.2 R19.2 U2.12 | length 194.7
  Top Layer w8: U2.12 567.61,440.59 603.5,476.49 R19.2 R18.2
NetR19_1: R19.1 U2.8 U2.9 | length 374.7
  Top Layer w8: U2.8 471.77,338.23 465,345 465,356.14 472.68,363.82 U2.9 578.82,363.82 585,370 585,435.36 659.64,510 R19.1
NetR27_1: R27.1 U4.4 | length 101.3
  Bottom Layer w8: U4.4 R27.1
NetR32_2: R32.2 U4.11 | length 247.6
  Bottom Layer w12: R32.2@203.5,580 R32.2@206.82,580 ; R32.2@213.97,590 290,666.03 290,713.32 248.32,755 U4.11
POSITION_FB: D11.2 J2.2 R3.2 U1.6 | length 843.6
  Top Layer w8: R3.2 135,819.54 142.31,819.54 200,761.85 200,750 207.4,742.6 U1.6 275.77,742.6 v1(288.76,755.59) v1(288.76,811.24)
  Bottom Layer w8: v1(288.76,755.59) 310,734.36 310,677.02 357.02,630 443.35,630 D11.2
  Bottom Layer w15: v1(288.76,811.24) 337.53,860 460,860 473,873 J2.2
STATUS: D10.2 R37.1 U4.12 | length 514.7
  Bottom Layer w8: R37.1 177.09,780.59 U4.12 309.41,780.59 330,760 330,686 370,646 477.35,646 D10.2
VIN: C3.2 C6.2 C8.1 C11.2 D1.1 J2.3 R2.2 R3.1 R17.1 R18.1 R21.1 R22.1 R37.2 U2.4 U3.5 U4.7 | length 1209.7
  Top Layer w12: C3.2 251.5,415 U2.4
  Top Layer w15: C3.2 215,361.5 215,238.35 D1.1 243.35,178.35 v2(225,160)
  Top Layer w20: R2.2 R3.1 132.32,889.17 v1(132.32,927.32) ; v1@622.35,615 655,615 666.5,603.5 R18.1 ; v1(645,720) 693.98,720 R21.1 698.98,647.52 R22.1
  Bottom Layer w12: U4.7 479.04,678.23 490.82,690 C8.1 ; v1(488,520) 488,497.99 540.99,445 C6.2
  Bottom Layer w15: v2(58,778.5) 68.5,768 R37.2 ; U3.5 548.5,388.15 C6.2
  Bottom Layer w20: C11.2 405,378.5 v1(405,405) 405,431.5 R17.1 ; C8.1 543.5,682.95 575,651.46 v1(575,645)
  other v1: 620,615
pads on no net: U4.1 U4.6 U4.10 U4.14

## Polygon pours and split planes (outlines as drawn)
GND on Bottom Layer "Bottom Layer-No Net" (solid, remove dead copper, pour order 21): 100,595 100,645 110,655 165,655 170,660 170,695 160,705 45,705 35,695 35,600 50,595
COIL+ on Bottom Layer "Bottom Layer-No Net" (solid, remove dead copper, pour order 23): 810,465 800,455 800,295 750,245 750,100 765,85 880,85 895,100 895,360 915,380 915,455 905,465
NetF1_2 on Bottom Layer "Bottom Layer-No Net" (solid, remove dead copper, pour order 19): 1015,95 930,95 913,112 913,313 915,315 1040,315 1045,310 1045,225 1025,205 1025,105
NetC9_2 on Bottom Layer "Bottom Layer-No Net" (solid, remove dead copper, pour order 24): 245,450 185,450 150,485 115,485 100,500 100,560 55,560 55,410 65,400 165,400 185,380 185,190 190,185 245,185 250,190 250,285 245,290
COIL- on Bottom Layer "Bottom Layer-No Net" (solid, remove dead copper, pour order 16): 265,500 370,500 380,490 380,345 395,330 450,330 525,255 705,255 720,240 720,95 710,85 645,85 640,90 635,155 600,190 490,190 470,210 365,210 355,220 355,275 340,290 280,290 265,305
GND on Bottom Layer "Bottom Layer-No Net" (solid, remove dead copper, pour order 18): 50,35 35,50 35,100 45,110 165.26,110 180.26,95 505,95 535,125 600,125 610,115 610,40 605,35
NetC9_1 on Bottom Layer "Bottom Layer-No Net" (solid, remove dead copper, pour order 25): 280,265 280,180 315,145 440,145 440,190 360,190 330,220 330,260 325,265
COIL+ on Top Layer "Bottom Layer-No Net" (solid, remove dead copper, pour order 26): 725,430 725,270 755,240 755,95 770,80 870,80 875,85 875,250 855,270 855,350 850,355 805,355 793,367 793,427 780,440 735,440
GND on Top Layer "Bottom Layer-No Net" (solid, remove dead copper, pour order 22): 615,105 625,95 625,40 620,35 50,35 35,50 35,160 85,160 85,120 100,105
GND on Top Layer "Bottom Layer-No Net" (solid, remove dead copper, pour order 29): 120,340 135,325 160,325 165,320 165,245 175,235 175,45 185,35 235,35 245,45 245,160 215,190 215,210 195,230 195,320 155,360 155,455 120,455
GND on MidLayer1 (GND) "Bottom Layer-No Net" (solid, remove dead copper, pour order 20): 60,35 1120,35 1145,60 1145,160 1145,940 1130.75,954.25 780,954.25 64.25,954.25 35,925 35,60 60,35
VIN on MidLayer2 (PWR) "Bottom Layer-No Net" (solid, remove dead copper, pour order 14): 60,35 35,60 35,925 64.25,954.25 875,954.25 895,925 895,800 790,695 790,385 789.98,310 790,295 765,270 535,270 460,345 395,345 385,355 385,505 365,525 255,525 250,520 250,280 255,275 325,275 330,270 330,225 350,205 450,205 470,185 600,185 630,155 630,45 620,35

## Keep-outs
Keep-Out Layer:
  text ".Layer_Name" at 132,-1113.49 h60

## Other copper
Top Layer:
  text ".Layer_Name" at 132,-1113.49 h60
MidLayer1 (GND):
  pour cut-out: 191.64,911.64 202.65,911.64 205,909.29 205,890 185,890 185,905
  pour cut-out: 205,928.58 205,890 225,870 490,870 500.28,880.28 500.28,934.72 490,945 221.42,945
  text ".Layer_Name" at 120,-1110 h60
MidLayer2 (PWR):
  pour cut-out: 185,911.64 208.36,911.64 210,910 205.54,905.54 205.54,890.88 204.66,890 185,890
  pour cut-out: 551,943 551,877 461.06,877 445.72,892.34 445.72,922.31 466.41,943
  pour cut-out: 358,877 219.42,877 202.14,894.28 202.14,925.72 221.42,945 358,945
  text ".Layer_Name" at 120,-1110 h60
Bottom Layer:
  text ".Layer_Name" at 132,-1113.49 h60

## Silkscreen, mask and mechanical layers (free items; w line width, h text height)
Top Overlay:
  circle w8: c289.29,518 r6.71
  lines w5: 102,566 107,571 107,594.72 115.02,602.73
  lines w6: 925,405 925,396 966,355
  text ".Layer_Name" at 132,-1113.49 h60
Bottom Overlay:
  circle w8: c612.72,644 r7.28
  circle w8: c707.9,735 r5.1
  circle w6: c452,639 r18
  circle w8: c656.71,420 r8.29
  circle w10: c495,835 r5
  circle w8: c1113,751 r26
  circle w8: c167,949 r26
  circle w6: c1133,200 r22
  circle w6: c235,340 r10
  lines w6: 30,615 30,945 70,945 ; 474,539 474,639 ; 475,505 475,476 602,476 ; 610,594 610,480 702,480 ; 644,650 750,650 ; 720,915 720,735 890,735 890,915 790,915 ; 740,480 790,480 790,548 ; 1079,721 1167,721 1167,590 1088,590 ; 1085,226 1166.1,226 1166.1,350 1085,350 1085,226
  text "B" at 177,933 h32
  text "B" at 1122,734 h46
  text "A" at 464,628 h40
  text "A" at 1147,187 h46
  text "TIDA-00289-E2" at 1163,29 h68
  text ".Layer_Name" at 132,-1113.49 h60
Top Paste:
  text ".Layer_Name" at 132,-1113.49 h60
Bottom Paste:
  text ".Layer_Name" at 132,-1113.49 h60
Top Solder:
  text ".Layer_Name" at 132,-1113.49 h60
  text ".Layer_Name" at 132,-1113.49 h60
Bottom Solder:
  text ".Layer_Name" at 132,-1113.49 h60
Drill Guide:
  text ".Layer_Name" at 132,-1113.49 h60
M1 Board Outline:
  the board outline again, w10
  text ".Layer_Name" at 105,-1115 h60
M2 Board Dimensions:
  rectangle: -445.5,-540.5 -320.5,-415.5
  rectangle: -320.5,-665.5 54.5,-540.5
  lines w7: -445.5,-540.5 554.5,-540.5 ; -320.5,-665.5 -320.5,-415.5 ; -195.5,-665.5 -195.5,-415.5 ; 54.5,-665.5 54.5,-415.5 ; 304.5,-665.5 304.5,-415.5 ; -445.5,-665.5 554.5,-665.5 554.5,-415.5 -445.5,-415.5 -445.5,-665.5
  lines w8: 0,30 1151.1,30 1151.1,954.25 0,954.25 ; 30,30 30,954.25
  lines w10: -445.5,-730.5 -445.5,-710.5 ; -385.5,-740.5 -445.5,-720.5 ; -385.5,-700.5 -445.5,-720.5 ; -221.42,-720.5 -445.5,-720.5 ; 330.42,-720.5 554.5,-720.5 ; 494.5,-740.5 554.5,-720.5 ; 494.5,-700.5 554.5,-720.5 ; 554.5,-730.5 554.5,-710.5
  text "1000 (mil)" at -211.42,-756.49 h60
M3 3D STEP Top:
  text ".Layer_Name" at 132,-1113.49 h60
M4 3D STEP Bottom:
  text ".Layer_Name" at 132,-1113.49 h60
M5 Assembly Top:
  lines w10: -737,-1185.17 5863,-1185.17 ; -737,-981.83 5865,-981.83 ; -737,-778.5 -737,-1388.5 3268,-1388.5 5865,-1388.5 5865,-778.5 -736.5,-778.5 -736.5,-1388.5 839,-1388.5 ; 1728,-1388.5 1728,-778.5 ; 2995,-981.83 2995,-778.5 ; 3835,-981.83 3835,-778.5 ; 4457,-1395 4457,-1192.17
  text "COMPONENTS MARKED 'DNP' SHOULD NOT BE POPULATED." at 708.5,-573.5 h60
  text "ASSEMBLY VARIANT:" at 708,-689 h60
  text ".VariantName" at 1744,-689 h60
  text "PCB VIEWED FROM TOP SIDE" at -673.5,-910.67 h60
  text "BOARD #:" at 1803,-910.67 h60
  text ".PRJ_Number" at 2348.5,-910.67 h60
  text "REV:" at 3193,-910.67 h60
  text ".PCB_Rev" at 3484.5,-910.67 h60
  text "SVN REV:" at 4031,-910.67 h60
  text ".VersionControl_RevNumber" at 4537,-910.67 h60
  text "IGNORE ->" at -673.5,-1113.49 h60
  text "ASSEMBLY TOP" at 295,-1115 h60
  text "PLOT NAME =" at -673.5,-1319.34 h60
  text ".plot_File_Name" at 132,-1319.34 h60
  text "GENERATED    :" at 1805,-1319.34 h60
  text ".Print_Date" at 2674.5,-1319.34 h60
  text ".Print_Time" at 3403.5,-1319.34 h60
  text "TEXAS INSTRUMENTS" at 4668,-1319.34 h60
M6 Assembly Bottom:
  circle w8: c207.93,391 r7.07
  circle w8: c608,388 r10
  circle w8: c664.09,617 r7.91
  circle w8: c753.39,790 r10.61
  lines w10: -737.5,-982.33 5864.5,-982.33 ; -735.5,-1185.67 5864.5,-1185.67 ; 670.5,-1395.5 670.5,-1192.67 ; 1292.5,-982.33 1292.5,-779 ; 2132.5,-982.33 2132.5,-779 ; 3399.5,-1389 3399.5,-779 ; 4288.5,-1389 5864,-1389 5864,-779 -737.5,-779 -737.5,-1389 1859.5,-1389 5864.5,-1389 5864.5,-779
  text "COMPONENTS MARKED 'DNP' SHOULD NOT BE POPULATED." at 5657,-573 h60
  text ".VariantName" at 4613,-689 h60
  text "ASSEMBLY VARIANT:" at 5652,-689 h60
  text ".VersionControl_RevNumber" at 590.5,-911.17 h60
  text "SVN REV:" at 1096.5,-911.17 h60
  text ".PCB_Rev" at 1643,-911.17 h60
  text "REV:" at 1934.5,-911.17 h60
  text ".PRJ_Number" at 2779,-911.17 h60
  text "BOARD #:" at 3324.5,-911.17 h60
  text "PCB VIEWED FROM BOTTOM SIDE" at 5801,-911.17 h60
  text "IGNORE ->" at 2102.85,-1113.49 h60
  text "ASSEMBLY BOTTOM" at 1175,-1130 h60
  text "TEXAS INSTRUMENTS" at 459.5,-1319.84 h60
  text ".Print_Time" at 1724,-1319.84 h60
  text ".Print_Date" at 2453,-1319.84 h60
  text "GENERATED    :" at 3322.5,-1319.84 h60
  text ".plot_File_Name" at 4995.5,-1319.84 h60
  text "PLOT NAME =" at 5801,-1319.84 h60
M9 Title Sheet:
  drawing of 57 lines, arcs and shapes, not listed
  text "1" at 294.84,7781.5 h70
  text "2" at 2790.5,7781.5 h70
  text "3" at 5279.84,7781.5 h70
  text "4" at 7786.51,7781.5 h70
  text "5" at 10285.5,7781.5 h70
  text "6" at 12790.5,7781.5 h70
  text "A" at -861.5,6638.5 h70
  text "A" at 13938.5,6638.5 h70
  text "B" at -861.5,4258.5 h70
  text "B" at 13938.5,4258.5 h70
  text "C" at -861.5,1883.5 h70
  text "C" at 13938.5,1883.5 h70
  text "PROJECT TITLE:" at 10898.5,22.5 h45
  text ".PRJ_Title" at 10948.5,-110.83 h70
  text "DESIGNED FOR:" at 10898.5,-278.5 h45
  text ".PRJ_Customer" at 10948.5,-418.5 h70
  text "D" at -861.5,-486.5 h70
  text "D" at 13938.5,-486.5 h70
  text "FILE NAME:" at 10898.5,-578.5 h45
  text ".PCB_File_Name_No_Path" at 10948.5,-698.5 h70
  text "Texas Instruments (TI) and/or its licensors do not warrant the accuracy or completeness of this specification" at 5929,-860.34 h45
  text "ENGINEER:" at 10898.5,-868.5 h45
  text "LAYOUT BY:" at 12403.5,-868.5 h45
  text "or any information contained therein. TI and/or its licensors do not warrant that this design will meet" at 5884.01,-973 h45
  text ".PRJ_Engineer" at 10948.5,-1023.49 h70
  text ".PCB_Layout" at 12454,-1023.49 h70
  text "the specifications, will be suitable for your application or fit for any particular purpose, or will operate in" at 5884.01,-1085.67 h45
  text "ALTIUM DESIGNER VERSION:" at 12403.5,-1178.5 h45
  text "an implementation. TI and/or its licensors do not warrant that the design is production worthy. You should" at 5884.01,-1198.33 h45
  text "completely validate and test your design implementation to confirm the system functionality for your application." at 5929,-1311 h45
  text ".print_Scale" at 10948.5,-1311.83 h70
  text ".Application_BuildNumber" at 12454,-1311.83 h70
  text "1" at 294.84,-1518.5 h70
  text "2" at 2790.5,-1518.5 h70
  text "3" at 5279.84,-1518.5 h70
  text "4" at 7786.51,-1518.5 h70
  text "5" at 10285.5,-1518.5 h70
  text "6" at 12790.5,-1518.5 h70
M10 Fab Notes:
  drawing of 228 lines, arcs and shapes, not listed
  text "DESIGN INFORMATION" at 11936.02,6555 h60
  text "(REFER ALSO ARRAY/PANEL PROFILING INFORMATION)" at 11574.46,6393.29 h60
  text "BOARD SIZE" at 10888.46,6389 h60
  text "30mm" at 11350.78,6261.18 h60
  text "X" at 11856.46,6261.18 h60
  text "25mm" at 12087.78,6261.18 h60
  text "Number of Layers :" at 11291.46,6064 h60
  text "4" at 12386.27,6054 h60
  text "MIN. TRACK WIDTH:" at 11291.46,5925 h60
  text "8" at 12387.7,5925 h60
  text "MIL" at 12542.46,5925 h60
  text "MIN. CLEARANCE:" at 11291.46,5793 h60
  text "MIL" at 12542.46,5793 h60
  text "7.99" at 12227,5789 h60
  text "MIN. VIA PAD SIZE:" at 11291.46,5661 h60
  text "26" at 12357.71,5661 h60
  text "MIL" at 12542.46,5661 h60
  text "EXTERNAL" at 12955,5520 h60
  text "0.101mm (4 MIL)" at 11986.46,5519.29 h60
  text "MINIMUM ANNULAR RING" at 10962.23,5515 h60
  text "PER" at 11162.23,5397 h60
  text "IPC-D-275 CLASS 2 LEVEL C" at 11382.23,5397 h60
  text "MIL, HOLES" at 12870.46,5284.71 h60
  text "+/-" at 12478,5284 h60
  text "+/-" at 13332,5284 h60
  text "REGISTRATION TOLERANCES:" at 10962.23,5279 h60
  text "METAL" at 12162,5279 h60
  text "5" at 12738.2,5279 h60
  text "3" at 13571.2,5279 h60
  text "MIL" at 13687.46,5279 h60
  text "MATERIAL:" at 10887.46,5069.54 h60
  text "FR-4 High Tg" at 11873.9,4929.21 h60
  text "X" at 11161.46,4920.64 h60
  text "FR-408" at 11308.46,4920.64 h60
  text "OTHER" at 12796.46,4920.64 h60
  text "63 MIL (1.6mm) +/-10%" at 11628.56,4757.92 h60
  text "THICKNESS:" at 10962.23,4753.64 h60
  text "X" at 11500.4,4753.64 h60
  text "OTHER" at 12913.46,4753.64 h60
  text "TOLERANCE:" at 10962.23,4595.64 h60
  text "X" at 11801.53,4595.64 h60
  text "ANSI IPC-6012 TYPE 3 CLASS 2" at 11988.48,4595.64 h60
  text "OTHER +/-" at 11988.46,4439.64 h60
  text "BOW & TWIST:" at 10962.23,4282.64 h60
  text "X" at 11801.53,4282.64 h60
  text "ANSI IPC-6012 TYPE 3 CLASS 2" at 11988.48,4282.64 h60
  text "OTHER +/-" at 11988.46,4124.13 h60
  text "COPPER THICKNESS (FINISHED):" at 10887.46,3988.64 h60
  text "1.4MIL (1oz)" at 11767.46,3835.92 h60
  text "2MIL (1.4oz)" at 12534.46,3835.92 h60
  text "2.8MIL (2oz)" at 13261.46,3835.92 h60
  text "OUTER:" at 11244.46,3831.64 h60
  text "X" at 11639,3831 h60
  text "1.4MIL (1oz)" at 11767.46,3678.92 h60
  text "2.8MIL (2oz)" at 12534.46,3678.92 h60
  text "N/A" at 13261,3679.29 h60
  text "INNER SIGNAL:" at 10955.38,3674.64 h60
  text "X" at 11639,3674 h60
  text "DRILLING:" at 10887.46,3535.64 h60
  text "REFERENCE:" at 10962.23,3418.64 h60
  text "X" at 11610.46,3418.64 h60
  text "AS SHOWN" at 11797.46,3418.64 h60
  text "X" at 12511.46,3418.64 h60
  text "NC_DRILL FILES" at 12648.46,3418.64 h60
  text "PTH MIN COPPER THICKNESS:" at 10962.23,3260.64 h60
  text "X" at 12312.46,3260.64 h60
  text "1MIL" at 12449.46,3260.64 h60
  text "OTHER" at 12946.46,3260.64 h60
  text "BOARD FINISH:" at 10887.46,3101.64 h60
  text "X" at 12496.46,2988.64 h60
  text "SILKSCREEN:" at 11042.68,2983.64 h60
  text "X" at 11991.46,2983.64 h60
  text "TOP" at 12117.46,2983.64 h60
  text "BOTTOM" at 12628.46,2983.64 h60
  text "SILKSCREEN COLOR:" at 11042.68,2816.64 h60
  text "X" at 11990.42,2816.64 h60
  text "WHITE" at 12117.46,2816.64 h60
  text "OTHER" at 12628.46,2816.64 h60
  text "SOLDER RESIST COLOR:" at 11042.68,2646.64 h60
  text "X" at 11610.42,2487.44 h60
  text "GREEN" at 11737.46,2487.44 h60
  text "BLUE" at 12328.46,2487.44 h60
  text "OTHER" at 12866.46,2487.44 h60
  text "IMMERSION GOLD (ENIG)" at 11948.46,2298.92 h60
  text "ENEPIG" at 13286,2295.64 h60
  text "SURFACE FINISH:" at 10887.46,2294.64 h60
  text "X" at 11761.51,2294.64 h60
  text "IMM. TIN/SILVER OR EQUIV" at 11217,2137.64 h60
  text "OTHER" at 12648.46,2137.64 h60
  text "ARRAY/PANEL:" at 10887.46,1958.64 h60
  text "CUT AND TRIM PER MECH LAYER 1" at 11948.46,1954.35 h60
  text "N.C. ROUTE" at 11948.46,1802.64 h60
  text "X" at 12627.46,1802.64 h60
  text "V. SCORE" at 12814.46,1802.64 h60
  text "CERTIFICATION:" at 10887.46,1665.64 h60
  text "MATERIALS AND WORKMANSHIP FOR ALL PCBS" at 11612.46,1665.64 h60
  text "TO MEET OR EXCEED THE REQUIREMENTS OF:" at 11612.46,1567.64 h60
  text "X" at 11238.96,1431.13 h60
  text "ANSI IPC-A-600F CLASS ->" at 11377.96,1431.13 h60
  text "X" at 13017.02,1431.13 h60
  text "2" at 13135.96,1431.14 h60
  text "1" at 12820.96,1429.64 h60
  text "3" at 13489.96,1429.64 h60
  text "X" at 11241.02,1271.64 h60
  text "UL 94V-0" at 11377.96,1271.64 h60
  text "X" at 12053.02,1271.64 h60
  text "RoHS" at 12189.96,1271.64 h60
  text "OTHER" at 12834.36,1271.64 h60
  text "PER ORDER" at 13231.42,1271.64 h60
  text "VIA TENTING:" at 12068,1134 h60
  text "X" at 12856.29,1134.11 h60
  text "ADDITIONAL REQUIREMENTS:" at 10887.46,1130.64 h60
  text "YES" at 12639.67,1124.92 h60
  text "NO" at 13034.47,1124.69 h60
  text "MICROSECTION:" at 10962.23,1015.64 h60
  text "YES" at 11867.96,1015.64 h60
  text "IMPEDANCE CONTROL:" at 12121,990 h60
  text "YES" at 13089,989 h60
  text "X" at 13647,982 h60
  text "NO" at 13480.47,971.69 h60
  text "REQUIRED" at 12719.46,843.49 h60
  text "BARE BOARD ELEC. TEST:" at 10952.23,840.64 h60
  text "NONE" at 12257.96,840.64 h60
  text "X" at 12592.46,840.64 h60
  text "PER ORDER" at 13311.46,840.64 h60
  text "MANUFACTURER'S UL:" at 10952.23,683.64 h60
  text "RAIL" at 12117.96,679.35 h60
  text "METAL" at 12609.77,679.35 h60
  text "X" at 12985,679 h60
  text "SILK" at 13121.46,679.35 h60
M11 Gerber Information:
  lines w10: -737,-1185.17 5863,-1185.17 ; -737,-981.83 5865,-981.83 ; -737,-778.5 -737,-1388.5 3268,-1388.5 5865,-1388.5 5865,-778.5 -736.5,-778.5 -736.5,-1388.5 839,-1388.5 ; 1728,-1388.5 1728,-778.5 ; 2995,-981.83 2995,-778.5 ; 3835,-981.83 3835,-778.5 ; 4457,-1395 4457,-1192.17
  text "ALL ARTWORK VIEWED FROM TOP SIDE" at -673.5,-910.67 h60
  text "BOARD #:" at 1803,-910.67 h60
  text ".PRJ_Number" at 2348.5,-910.67 h60
  text "REV:" at 3193,-910.67 h60
  text ".PCB_Rev" at 3484.5,-910.67 h60
  text "SVN REV:" at 4031,-910.67 h60
  text ".VersionControl_RevNumber" at 4537,-910.67 h60
  text "LAYER NAME =" at -673.5,-1113.49 h60
  text "PLOT NAME =" at -673.5,-1319.34 h60
  text ".plot_File_Name" at 132,-1319.34 h60
  text "GENERATED    :" at 1805,-1319.34 h60
  text ".Print_Date" at 2674.5,-1319.34 h60
  text ".Print_Time" at 3403.5,-1319.34 h60
  text "TEXAS INSTRUMENTS" at 4668,-1319.34 h60
M12 Stackup:
  lines w6: 10893,7429.5 13764,7429.5 ; 10893,7542.1 13764,7542.1 ; 10833,6717 ccw(c10869,6717) 10869,6681 13788,6681 ccw(c13788,6717) 13824,6717 13824,7639 ccw(c13788,7639) 13788,7675 10869,7675 ccw(c10869,7639) 10833,7639 10833,6717
  text "Layer Stack Up Detail for: TIDA-00289.PcbDoc" at 10893,7570.75 h51
  text "Layer" at 10893,7500.1 h26
  text "Gerber" at 11897.8,7500.1 h26
  text "Copper" at 12556.85,7500.1 h26
  text "Dielectric" at 13258.35,7500.1 h26
  text "Name" at 10893,7448.1 h26
  text "Document" at 11897.8,7448.1 h26
  text "Thickness" at 12556.85,7448.1 h26
  text "Material" at 13258.35,7448.1 h26
  text "Top Solder Mask" at 10893,7374.73 h36
  text "(.GTS)" at 11897.8,7374.73 h36
  text "Solder Resist" at 13258.35,7374.73 h36
  text "Top Layer" at 10893,7271.19 h36
  text "(.GTL)" at 11897.8,7271.19 h36
  text "1.4mil" at 12556.85,7271.19 h36
  text "FR-4" at 13258.35,7219.42 h36
  text "MidLayer1 (GND)" at 10893,7167.65 h36
  text "(.G1)" at 11897.8,7167.65 h36
  text "1.4mil" at 12556.85,7167.65 h36
  text "FR-4" at 13258.35,7115.88 h36
  text "MidLayer2 (PWR)" at 10893,7064.1 h36
  text "(.G2)" at 11897.8,7064.1 h36
  text "1.4mil" at 12556.85,7064.1 h36
  text "FR-4" at 13258.35,7012.33 h36
  text "Bottom Layer" at 10893,6960.56 h36
  text "(.GBL)" at 11897.8,6960.56 h36
  text "1.4mil" at 12556.85,6960.56 h36
  text "Bottom Solder Mask" at 10893,6857.02 h36
  text "(.GBS)" at 11897.8,6857.02 h36
  text "Solder Resist" at 13258.35,6857.02 h36
M13 Component Bodies Top:
  text ".Layer_Name" at 132,-1113.49 h60
M14 Component Bodies Bottom:
  text ".Layer_Name" at 132,-1113.49 h60
M15 Courtyards Top:
  text ".Layer_Name" at 132,-1113.49 h60
M16 Courtyards Bottom:
  text ".Layer_Name" at 132,-1113.49 h60
Drill Drawing:
  text ".legend" at 1855,485 h60
  text "Drill Table" at 1865,315 h60
  text "DRILL TOLERANCE" at 1859.72,201.52 h60
  text "FOR PTH +/- 3MIL" at 1860.14,92.09 h60
  text "12mil drill:+0/-12mil" at 1855,-30 h60
  text "16mil drill:+0/-16mil" at 1860,-155 h60
  text ".Layer_Name" at 132,-1113.49 h60

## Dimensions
0,0 to 1181.1,0 on M1 Board Outline
0,0 to 0,984.25 on M1 Board Outline
0,0 to 1181.1,0 on Drill Drawing
0,0 to 0,984.25 on Drill Drawing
